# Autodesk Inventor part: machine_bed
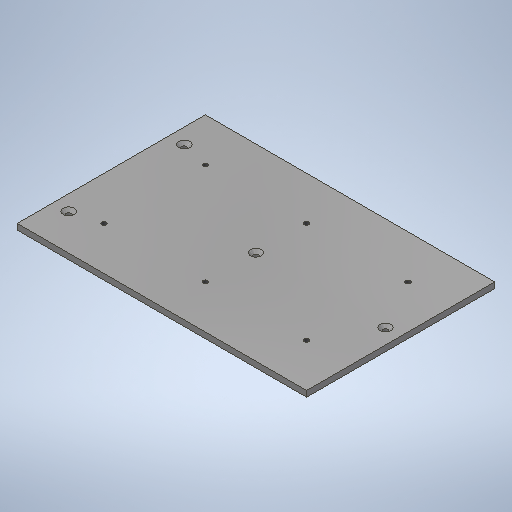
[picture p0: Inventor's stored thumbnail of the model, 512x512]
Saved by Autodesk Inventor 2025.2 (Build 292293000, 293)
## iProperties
Created: 2025-04
Part Number: machine_bed
Material: 1.0037 S235JR
Document SubType Name: Modeling
Designer: BennF
Density: 7.85 g/cm^3
Appearance: Stahl
Author: BennF
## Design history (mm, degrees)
sketch "Sketch2"
  geometry: L1 (-100, 65)-(100, 65); L2 (100, 65)-(100, -65); L3 (100, -65)-(-100, -65); L4 (-100, -65)-(-100, 65); 3 further points
  constraints: 8 end point, 2 midpoint, 2 parallel, 1 horizontal, 1 horizontal alignment, 1 perpendicular, 1 vertical alignment
  dimensions: "d0" = 200 distance of L1.start L1.end; "d1" = 130 distance of L3.end L1.start
extrude "Extrusion1" new body sketch "Sketch2" distance "d2" = 4; taper "d3" = 0 deg
sketch "Sketch3"
  geometry: L1 (-89.5, 40)-(-89.5, -40); L2 (-89.5, 0)-(0, 0); L3 (0, 0)-(89.5, 0); L4 (-100, 65)-(-100, -65) reference; L5 (100, 65)-(-100, 65) reference; 1 further point
  constraints: 6 end point, 2 collinear, 2 horizontal alignment, 1 coincident, 1 horizontal, 1 midpoint, 1 vertical, 1 vertical alignment
  dimensions: "d13" = 10.5 distance from line of L2.start L4; "d23" = 25 distance from line of L1.start L5
hole "Hole1" sketch "Sketch3" at (-89.5, 40), (-89.5, -40), (0, 0), (89.5, 0) diameter "d4" = 3.4; stored, may be unused: countersink angle "d8" = 90 deg, drill point angle "d10" = 0 deg; dims "d5" = 6, "d6" = 7.5, "d7" = 6.7, "d9" = 8
sketch "Sketch4"
  geometry: L1 (-70, 35)-(70, 35); L2 (70, 35)-(70, -35); L3 (70, -35)-(-70, -35); L4 (-70, -35)-(-70, 35); L5 (100, 65)-(-100, 65) reference; L6 (-100, 65)-(-100, -65) reference; 7 further points
  constraints: 8 end point, 5 horizontal alignment, 5 vertical alignment, 2 midpoint, 2 parallel, 1 horizontal, 1 perpendicular
  dimensions: "d21" = 30 distance between parallel lines of L1 L5; "d22" = 30 distance between parallel lines of L6 L4 (= d21)
hole "Hole2" sketch "Sketch4" at (-70, 35), (0, 35), (70, 35), (-70, -35), (0, -35), (70, -35) diameter "d14" = 3.242; stored, may be unused: countersink angle "d18" = 90 deg, drill point angle "d20" = 118 deg; dims "d15" = 8, "d16" = 7.5, "d17" = 2, "d19" = 8
body "Solid1"
